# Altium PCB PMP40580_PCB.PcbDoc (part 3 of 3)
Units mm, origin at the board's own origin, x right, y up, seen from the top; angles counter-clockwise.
Board outline 215 x 165 mm, 2 copper layers (Top Layer, Bottom Layer), stack 1.575 mm thick; 235 components, 90 nets, 527 pads, 0 vias.
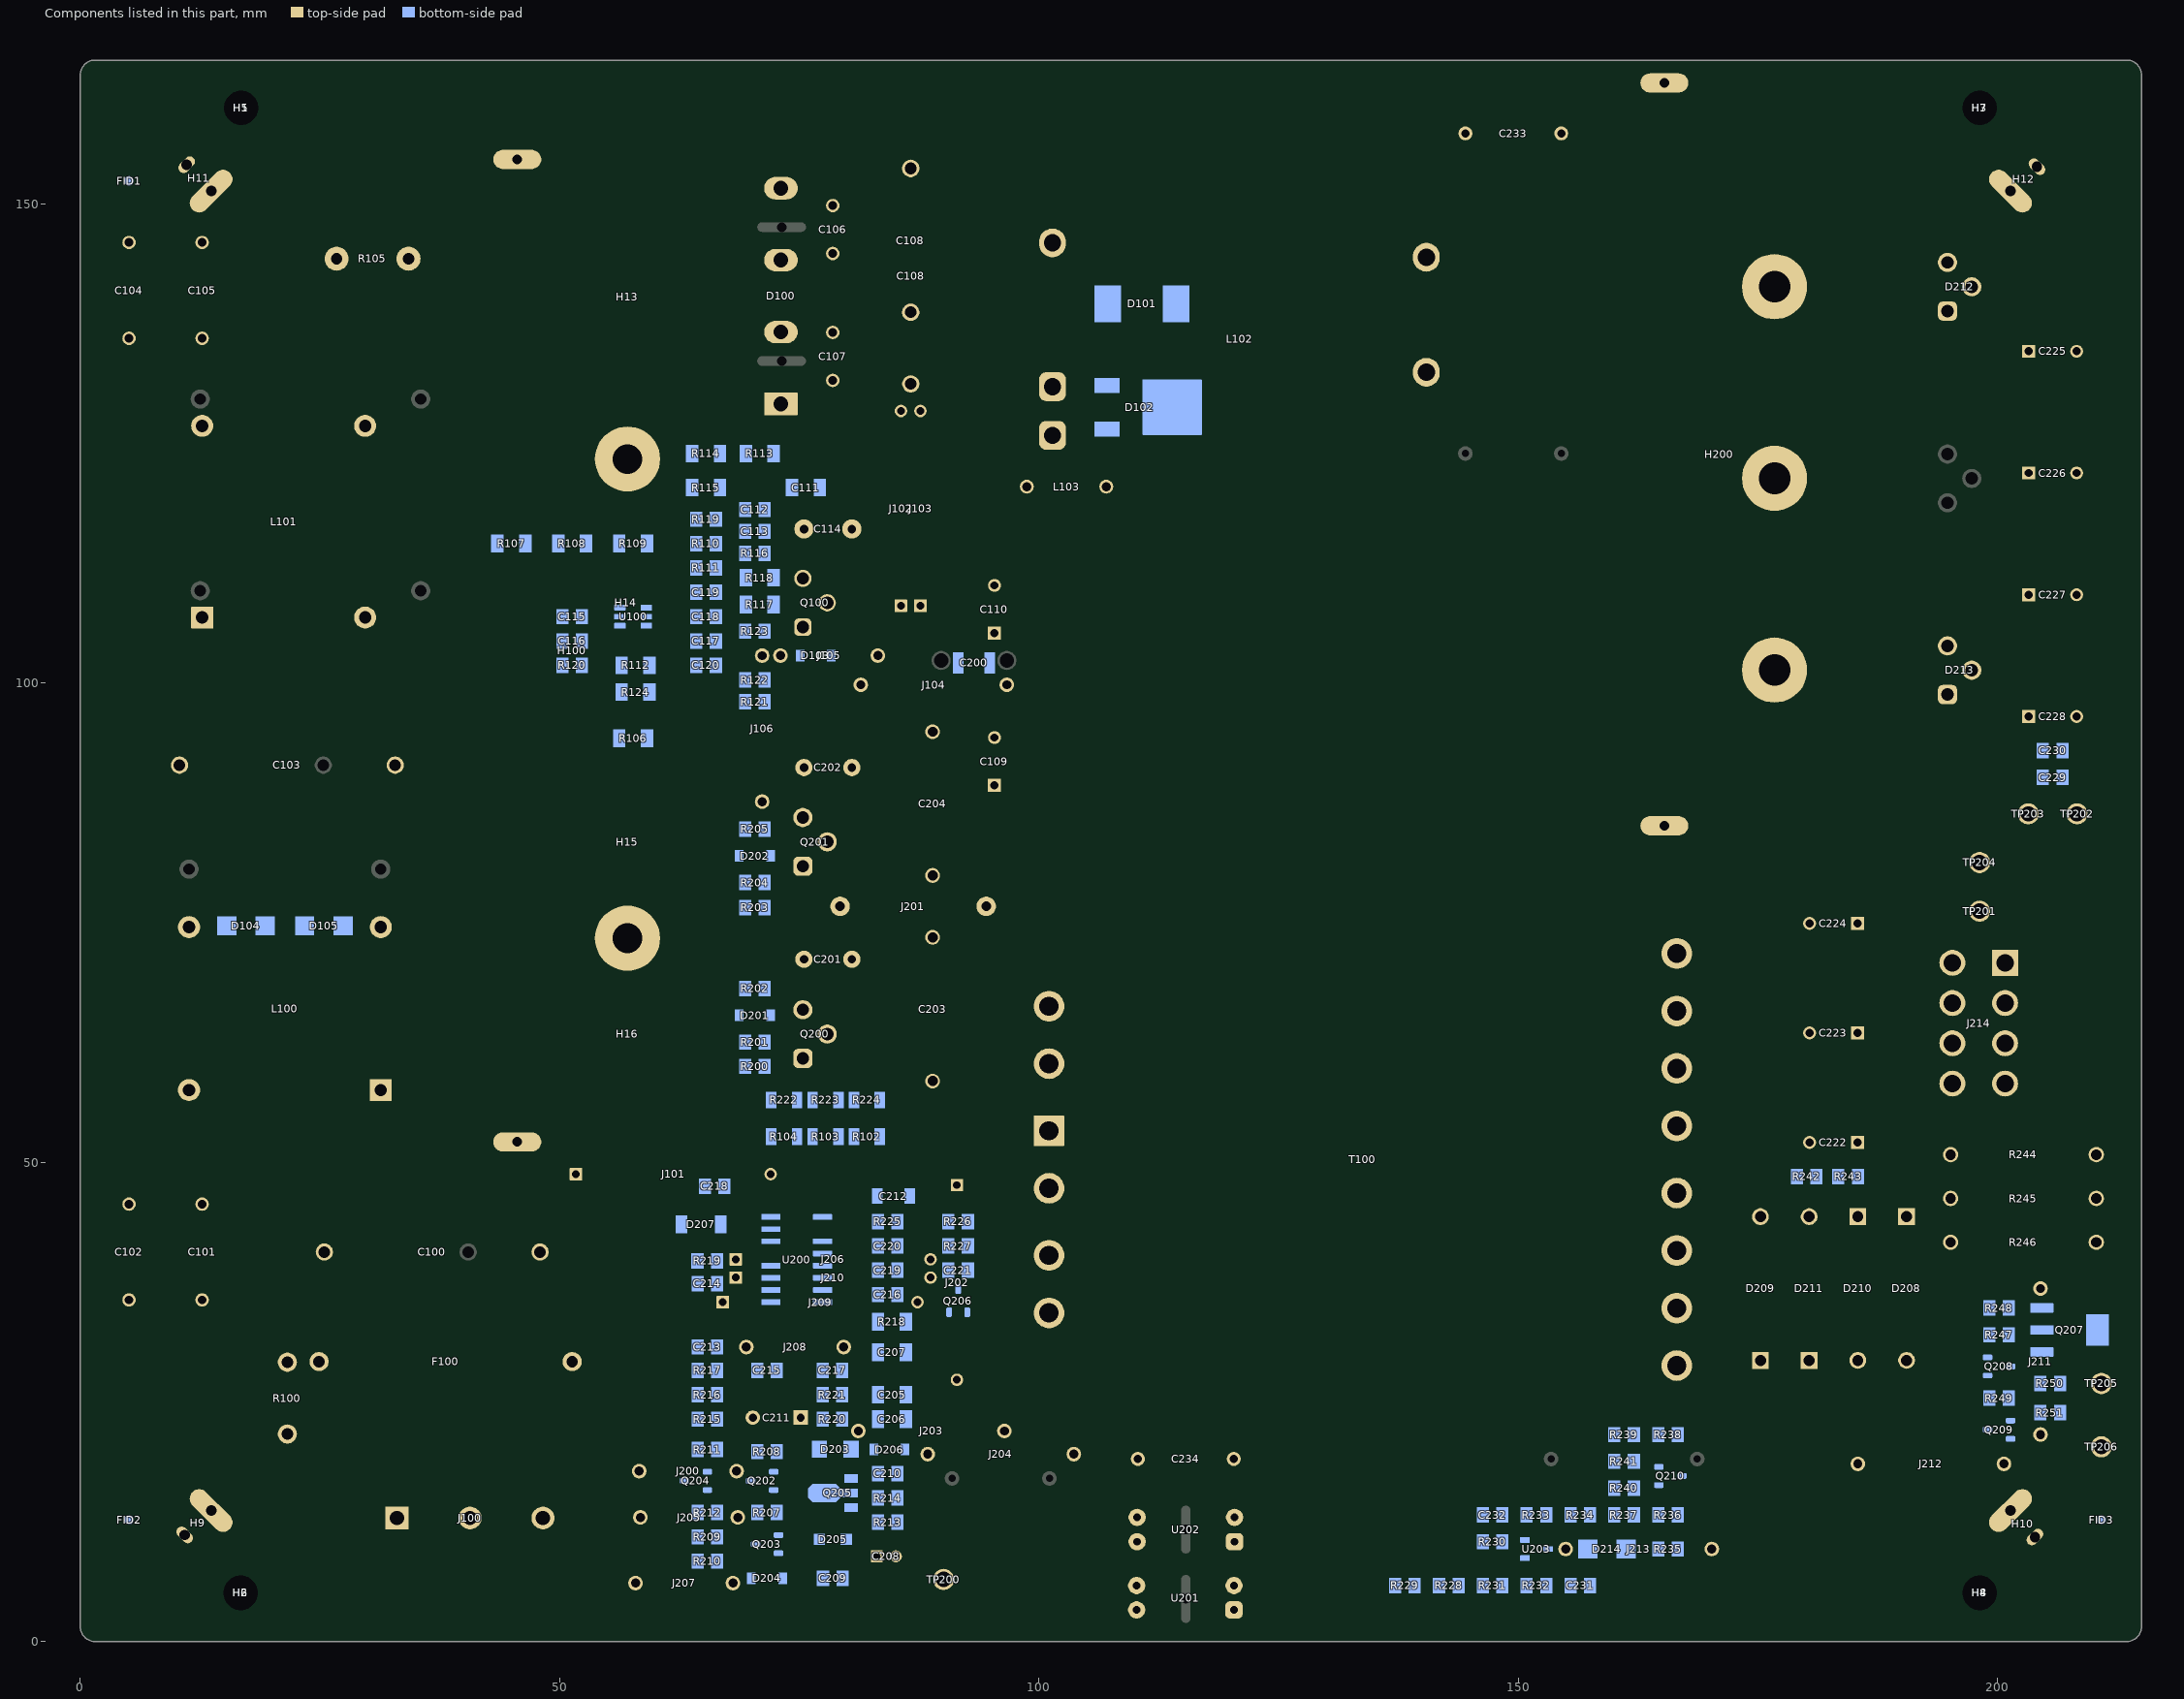
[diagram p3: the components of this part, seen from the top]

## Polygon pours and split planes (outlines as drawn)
PGND on Bottom Layer "Bottom Layer-No Net 15" (solid, pour order 78): 97.028,20.574 98.552,22.098 98.552,35.306 100.076,36.83 110.998,36.83 110.998,16.002 110.236,15.24 97.79,15.24 97.028,16.002
PGND on Bottom Layer "Bottom Layer-PGND" (solid, remove dead copper, pour order 70): 67.421,115.316 76.2,106.661 76.2,52.705 81.661,47.244 91.948,47.244 91.948,4.445 55.88,4.445 55.88,55.88 52.07,59.69 52.07,106.045 63.119,106.045 63.754,106.68 63.754,115.316
NetC112_2 on Bottom Layer "Source" (solid, remove dead copper, pour order 18): 73.406,106.934 76.725,110.253 76.725,111.196 76.454,111.467 76.454,114.554 72.136,118.872 70.824,118.872 70.87,107.438 71.374,106.934
PGND on Bottom Layer "Bottom Layer-PGND2" (solid, remove dead copper, pour order 68): 139.065,85.09 148.59,85.09 150.749,87.249 150.749,99.568 150.749,114.3 145.415,119.634 145.415,165 72.036,165 69.596,162.56 69.596,149.606 70.358,148.844 79.375,148.844 82.55,152.019 82.55,157.48 86.36,161.29 135.89,161.29 139.065,158.115
VCC on Bottom Layer "Bottom Layer-VCC" (solid, remove dead copper, pour order 66): 78.105,9.144 78.105,11.099 76.107,13.096 76.107,20.828 78.867,20.828 78.867,14.608 78.867,9.512 78.981,9.398 82.169,9.398 84.836,12.065 84.836,15.24 85.09,15.494 85.471,15.494 85.725,15.24 85.725,10.668 83.058,8.001 79.248,8.001
NetC117_1 on Bottom Layer "Bottom Layer-PFCVCC" (solid, remove dead copper, pour order 62): 58.801,106.426 58.547,106.172 58.547,102.108 59.817,100.838 64.643,100.838 64.643,104.394 62.611,106.426
SGND on Bottom Layer "Bottom Layer-No Net 12" (solid, remove dead copper, pour order 56): 14.478,16.51 13.462,17.526 13.462,32.004 17.018,35.56 17.018,36.83 16.51,37.338 0,37.338 0,0 22.098,0 22.098,8.89
SGND on Bottom Layer "Bottom Layer-No Net 12" (solid, remove dead copper, pour order 54): 0,144.399 15.444,144.399 16.637,145.592 16.637,151.892 22.86,158.115 22.86,165 0,165
NetC106_2 on Bottom Layer "Bottom Layer-No Net 10" (solid, remove dead copper, pour order 52): 79.756,145.034 78.994,145.796 69.342,145.796 67.818,147.32 33.274,147.32 32.512,146.558 32.512,143.256 33.274,142.494 79.212,142.494 79.756,143.038
NetC107_1 on Bottom Layer "Bottom Layer-No Net 11" (solid, remove dead copper, pour order 50): 79.756,135.89 79.269,135.403 69.109,135.403 67.056,133.35 55.626,133.35 39.476,117.2 39.476,110.342 33.274,104.14 28.575,104.14 26.67,106.045 26.67,111.76 37.084,122.174 53.086,138.176 79.248,138.176 79.756,137.668
NetD102_1 on Bottom Layer "Bottom Layer-No Net" (solid, pour order 24): 106.426,119.38 105.801,120.005 105.801,132.471 106.172,132.842 108.204,132.842 108.712,132.334 108.712,119.38
PGND on Bottom Layer "Bottom Layer-No Net" (solid, remove dead copper, pour order 8): 83.566,108.288 87.038,111.76 93.218,111.76 96.11,111.76 96.52,111.35 96.52,109.347 95.885,108.712 93.98,108.712 92.202,106.934 92.202,99.314 96.52,94.996 96.52,93.345 95.631,92.456 84.836,92.456 83.185,94.107 79.514,94.107 77.47,92.063 77.47,90.932 77.47,85.836 76.216,84.582 74.906,84.582 72.898,86.59 72.898,91.44 78.486,97.028 80.264,98.806 80.264,101.346 80.264,104.986
HS on Bottom Layer "HS" (solid, pour order 6): 79.502,84.582 79.502,80.264 73.406,74.168 69.469,74.168 68.707,73.406 68.707,70.739 74.676,64.77 76.458,64.77 78.359,66.671 78.359,73.533 81.28,76.454 81.28,86.614 81.28,92.075 79.883,92.075 79.502,91.694
HS on Bottom Layer "Bottom Layer-No Net" (solid, pour order 4): 98.425,64.806 98.425,59.055 99.441,58.039 102.997,58.039 104.14,59.182 104.14,64.77 104.14,76.18 101.602,78.74 93.726,78.74 92.837,77.851 92.837,74.803 98.425,69.215
NetC203_2 on Bottom Layer "Bottom Layer-No Net" (solid, pour order 2): 102.87,55.88 103.378,55.88 104.14,55.118 104.14,51.562 103.378,50.8 102.87,50.8 95.377,50.8 93.472,48.895 92.583,48.895 92.4,49.078 92.4,63.556 87.884,68.072 87.884,80.772 88.392,81.28 90.297,81.28 90.805,80.772 90.805,73.707 96.436,68.076 96.436,59.52 96.436,58.25 98.806,55.88
PFC_DC+ on Bottom Layer "PFC_DC" (solid, pour order 0): 135.255,86.995 133.604,85.344 102.108,85.344 100.076,83.312 87.122,83.312 85.852,82.042 85.852,66.818 90.17,62.5 90.17,57.15 89.789,56.769 88.011,56.769 85.344,59.436 80.628,59.436 77.47,62.594 77.47,64.262 79.502,66.294 79.502,71.755 83.312,75.565 83.312,85.852 87.884,90.424 97.155,90.424 98.679,91.948 98.679,95.631 94.234,100.076 94.234,106.68 97.028,106.68 110.744,120.396 110.744,138.43 110.883,138.569 110.883,156.603 112.395,158.115 133.35,158.115 135.255,156.21 135.255,105.791
NetC107_2 on Bottom Layer "Bottom Layer-No Net" (solid, pour order 10): 70.612,130.556 71.499,131.443 75.82,131.446 77.216,132.842 80.264,132.842 81.269,131.837 81.269,131.805 82.296,130.778 82.296,126.746 84.074,124.968 89.154,124.968 91.186,127 91.186,147.066 85.09,153.162 85.09,156.464 86.741,158.115 96.361,158.115 108.712,145.764 108.712,139.16 108.712,137.414 108.712,136.906 108.204,136.398 99.822,136.398 97.79,138.43 97.79,147.828 91.44,154.178 88.265,154.178 88.265,153.67 91.186,153.67 97.282,147.574 97.282,125.476 92.583,120.777 81.915,120.777 75.692,127 71.12,127 70.612,127.508
PGND on Bottom Layer "Bottom Layer-No Net" (solid, pour order 12): 70.358,148.844 69.596,149.606 69.596,154.178 70.358,154.94 80.01,154.94 88.9,146.05 88.9,127.635 88.265,127 84.94,127 84.328,127.612 84.328,143.764 79.248,148.844
NetC111_1 on Bottom Layer "Bottom Layer-No Net" (solid, pour order 14): 78.999,117.597 76.708,119.888 76.708,120.83 78.793,118.745 78.863,118.745 93.345,118.745 99.314,124.714 99.314,132.842 99.822,133.35 103.124,133.35 103.759,132.715 103.759,122.301 95.885,114.427 86.741,114.427 78.994,106.68 78.384,106.68 77.216,107.848 77.216,108.912 78.999,110.695
NetD208_2 on Bottom Layer "Bottom Layer-No Net 2" (solid, remove dead copper, pour order 32): 171.577,40.767 176.784,35.56 188.357,35.56 191.897,32.131 191.897,28.575 191.262,27.94 189.23,27.94 188.595,28.575 188.595,30.861 187.325,32.131 180.213,32.131 178.816,32.131 177.165,30.48 177.165,28.575 176.53,27.94 173.99,27.94 173.355,28.575 173.355,33.655 168.91,38.1 168.656,38.354 165.1,38.354 164.084,39.37 164.084,42.418 164.846,43.18 169.164,43.18 169.99,42.355
NetD210_2 on Bottom Layer "Bottom Layer-No Net 2" (solid, remove dead copper, pour order 34): 172.72,32.385 172.72,28.575 173.99,27.305 177.165,27.305 177.8,27.94 177.8,29.845 179.07,31.115 186.055,31.115 187.325,29.845 187.325,26.67 186.055,25.4 171.45,25.4 169.164,27.686 169.164,30.226 167.64,31.75 165.1,31.75 164.084,32.766 164.084,36.449 164.973,37.338 167.767,37.338
12V on Bottom Layer "Bottom Layer-No Net 3" (solid, remove dead copper, pour order 36): 197.612,145.288 198.374,146.05 203.2,146.05 205.232,144.018 205.232,84.582 204.47,83.82 198.374,83.82 197.612,84.582
150V on Bottom Layer "Bottom Layer-No Net 4" (solid, remove dead copper, pour order 38): 183.388,42.418 183.388,39.243 184.15,38.481 191.516,38.481 192.278,39.243 192.278,42.672 192.278,45.212 186.69,50.8 186.69,73.66 187.706,74.676 192.532,74.676 193.04,74.168 193.04,72.136 191.262,70.358 188.214,70.358 187.452,69.596 187.452,51.308 193.04,45.72 193.04,27.686 193.294,27.432 194.056,27.432 194.056,39.116 196.342,41.402 196.342,51.054 195.589,51.807 190.255,51.807 188.468,53.594 188.468,68.834 188.976,69.342 202.184,69.342 202.946,70.104 202.946,75.184 200.152,77.978 186.436,77.978 183.388,74.93
SGND on Bottom Layer "Bottom Layer-No Net 5" (solid, remove dead copper, pour order 40): 120.904,76.962 119.38,75.438 119.38,73.533 119.38,35.941 119.38,0 215,0 215,164.984 214.884,165.1 158.115,165.1 158.115,165 153.543,165 153.543,122.936 158.877,117.602 158.877,79.248 156.591,76.962
NetC103_2 on Bottom Layer "Bottom Layer-No Net 7" (solid, remove dead copper, pour order 42): 28.448,73.152 32.766,73.152 34.29,74.676 34.29,92.71 19.685,107.315 19.685,130.937 13.462,137.16 11.938,137.16 11.43,136.652 11.43,135.636 17.145,129.921 17.145,122.809 10.668,116.332 10.668,103.632 27.178,87.122 27.178,74.422
NetC103_1 on Bottom Layer "Bottom Layer-No Net 8" (solid, remove dead copper, pour order 44): 14.732,74.168 14.732,75.692 12.954,77.47 12.954,97.3 8.128,102.126 8.128,120.142 14.605,126.619 14.605,128.905 6.35,137.16 4.318,137.16 3.81,136.652 3.81,75.184 5.842,73.152 13.716,73.152
Neutral on Bottom Layer "Bottom Layer-No Net 9" (solid, remove dead copper, pour order 46): 38.862,10.16 42.164,10.16 43.18,11.176 43.18,27.94 49.53,34.29 49.53,41.656 25.146,66.04 8.128,66.04 3.81,61.722 3.81,44.704 4.318,44.196 6.687,44.196 7.366,44.875 7.366,59.944 9.652,62.23 23.495,62.23 38.608,47.117 38.608,26.416 35.814,23.622 20.828,23.622 20.066,22.86 20.066,20.32 20.828,19.558 36.068,19.558 37.846,17.78 37.846,11.176
NetD103_2 on Bottom Layer "Gate" (solid, remove dead copper, pour order 20): 74.294,106.906 74.449,107.061 76.387,107.061 76.514,106.934 78.74,104.708 78.74,102.362 73.66,97.282 70.612,97.282 70.612,98.895 72.927,98.895 76.962,102.93 76.962,103.378 75.718,104.622 70.751,104.622 70.751,106.057 70.866,106.172 73.56,106.172
NetC100_1 on Bottom Layer "Bottom Layer-No Net 6" (solid, remove dead copper, pour order 72): 20.828,27.178 26.67,27.178 27.94,28.448 27.94,51.435 19.685,59.69 10.922,59.69 9.906,58.674 9.906,44.958 10.668,44.196 13.716,44.196 14.478,44.958 14.478,49.022 12.192,51.308 12.192,55.626 12.954,56.388 17.272,56.388 23.622,50.038 23.622,33.02 20.066,29.464 20.066,27.94
Line on Bottom Layer "Bottom Layer-No Net 13" (solid, pour order 74): 51.816,10.16 52.832,11.176 52.832,29.972 52.07,30.734 50.038,30.734 45.72,26.416 45.72,11.176 46.736,10.16
NetL101_3 on Bottom Layer "Bottom Layer-No Net 14" (solid, pour order 76): 37.465,134.62 29.21,142.875 29.21,146.685 28.575,147.32 24.765,147.32 24.13,146.685 24.13,126.492 26.162,124.46 32.385,124.46 37.465,129.54

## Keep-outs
Keep-Out Layer:
  lines w0.127: 0,1.532 ccw(c1.532,1.532) 1.532,0 213.468,0 ccw(c213.468,1.532) 215,1.532 215,163.468 ccw(c213.468,163.468) 213.468,165 1.532,165 ccw(c1.532,163.468) 0,163.468 0,1.532 ; 2.758,5.174 ccw(c5.158,5.174) 5.158,2.774 ccw(c5.158,5.174) 7.558,5.174 ccw(c5.158,5.174) 5.158,7.574 ccw(c5.158,5.174) 2.758,5.174 ; 2.758,159.81 ccw(c5.158,159.81) 5.158,157.41 ccw(c5.158,159.81) 7.558,159.81 ccw(c5.158,159.81) 5.158,162.21 ccw(c5.158,159.81) 2.758,159.81 ; 74.964,62.976 cw(c75.368,63.38) 74.964,63.784 77.504,66.324 cw(c77.908,65.92) 78.312,65.516 76.176,63.38 78.312,61.244 cw(c77.908,60.84) 77.504,60.436 74.964,62.976 ; 74.964,83.03 cw(c75.368,83.434) 74.964,83.838 77.504,86.378 cw(c77.908,85.974) 78.312,85.57 76.176,83.434 78.312,81.298 cw(c77.908,80.894) 77.504,80.49 74.964,83.03 ; 74.964,107.976 cw(c75.368,108.38) 74.964,108.784 77.504,111.324 cw(c77.908,110.92) 78.312,110.516 76.176,108.38 78.312,106.244 cw(c77.908,105.84) 77.504,105.436 74.964,107.976 ; 194.236,140.947 cw(c194.64,141.351) 194.236,141.755 196.776,144.295 cw(c197.18,143.891) 197.584,143.487 195.448,141.351 197.584,139.215 cw(c197.18,138.811) 196.776,138.407 194.236,140.947 ; 194.241,120.881 cw(c194.645,121.285) 194.241,121.689 196.781,124.229 cw(c197.185,123.825) 197.589,123.421 195.453,121.285 197.589,119.149 cw(c197.185,118.745) 196.781,118.341 194.241,120.881 ; 194.363,100.942 cw(c194.767,101.346) 194.363,101.75 196.903,104.29 cw(c197.307,103.886) 197.711,103.482 195.575,101.346 197.711,99.21 cw(c197.307,98.806) 196.903,98.402 194.363,100.942 ; 207.418,5.174 ccw(c209.818,5.174) 209.818,2.774 ccw(c209.818,5.174) 212.218,5.174 ccw(c209.818,5.174) 209.818,7.574 ccw(c209.818,5.174) 207.418,5.174 ; 207.418,159.81 ccw(c209.818,159.81) 209.818,157.41 ccw(c209.818,159.81) 212.218,159.81 ccw(c209.818,159.81) 209.818,162.21 ccw(c209.818,159.81) 207.418,159.81
  lines w0.254: 0,1.532 ccw(c1.532,1.532) 1.532,0 213.468,0 ccw(c213.468,1.532) 215,1.532 215,163.468 ccw(c213.468,163.468) 213.468,165 1.532,165 ccw(c1.532,163.468) 0,163.468 0,1.532 ; 2.758,5.174 ccw(c5.158,5.174) 5.158,2.774 ccw(c5.158,5.174) 7.558,5.174 ccw(c5.158,5.174) 5.158,7.574 ccw(c5.158,5.174) 2.758,5.174 ; 2.758,159.81 ccw(c5.158,159.81) 5.158,157.41 ccw(c5.158,159.81) 7.558,159.81 ccw(c5.158,159.81) 5.158,162.21 ccw(c5.158,159.81) 2.758,159.81 ; 207.418,5.174 ccw(c209.818,5.174) 209.818,2.774 ccw(c209.818,5.174) 212.218,5.174 ccw(c209.818,5.174) 209.818,7.574 ccw(c209.818,5.174) 207.418,5.174 ; 207.418,159.81 ccw(c209.818,159.81) 209.818,157.41 ccw(c209.818,159.81) 212.218,159.81 ccw(c209.818,159.81) 209.818,162.21 ccw(c209.818,159.81) 207.418,159.81
  text ".Layer_Name" at 14.656,-51.321 h1.52

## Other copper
Top Layer:
  text ".Layer_Name" at 14.656,-51.321 h1.52
Bottom Layer:
  rectangle net SGND: 163.576,46.355 169.418,47.117
  rectangle net NetQ207_2: 203.2,31.496 211.328,33.528
  region net SGND: 166.878,46.228 166.878,49.7 166.116,49.7 166.116,46.228
  region net PGND: 140.746,142.342 140.746,146.957 139.984,146.957 139.984,142.342
  rectangle net PGND: 140.462,144.12 142.821,144.882
  region net PGND: 140.746,130.342 140.746,134.957 139.984,134.957 139.984,130.342
  rectangle net PGND: 140.208,132.12 142.821,132.882
  pour cut-out: 197.612,109.474 203.2,109.474 203.2,108.966 197.612,108.966
  region net NetD203_2: 78.867,24.003 80.645,24.003 81.915,22.733 81.915,21.209 80.264,19.558 79.502,19.558 79.502,21.717 78.867,22.352
  pour cut-out: 103.505,63.246 104.14,62.611 104.14,64.135 103.505,63.5 99.187,63.5 98.425,64.262 98.425,62.484 99.187,63.246
  region: 112.018,53.611
  region: 112.018,53.611
  region: 112.018,53.611
  region: 112.018,53.611
  region: 112.018,53.611
  region: 112.018,53.611
  pour cut-out: 103.251,128.27 103.378,128.27 103.759,127.889 103.759,128.768 103.388,128.397 99.695,128.397 99.314,128.778 99.314,127.889 99.695,128.27 99.822,128.27
  region net VCC: 82.195,8.011 82.427,8.011 84.08,9.664 83.651,10.093 82.864,10.093 82.195,9.424
  region net NetC211_1: 75.946,28.829 75.438,28.829 74.422,27.813 74.422,24.09 75.144,23.368 75.946,24.17
  region net RVCC: 71.882,22.479 69.977,20.574 69.977,17.217 68.834,16.074 68.834,15.621 69.977,14.478 69.977,12.7 71.247,12.7 71.247,20.574 73.66,22.987 73.66,27.813 74.93,29.083 74.93,31.534 74.46,31.534 71.882,28.956
  region net PS_ON: 142.621,4.064 142.621,4.572 142.748,4.699 142.875,4.699 145.034,2.54 145.034,2.286 144.399,2.286
  pour cut-out: 94.996,83.312 94.996,87.63 95.504,87.63 95.504,83.312
  region net DRV: 68.326,97.536 68.834,98.044 68.834,101.092 69.596,101.092 69.977,100.711 69.977,97.282 69.723,97.028 58.674,97.028 58.166,97.536 58.166,97.79 58.166,103.124 57.404,103.886 57.404,105.484 57.404,106.426 57.201,106.629 55.601,106.629 55.499,106.731 55.499,107.137 55.601,107.239 55.617,107.239 57.506,107.239 57.892,106.852 57.892,104.033 58.42,103.505 58.42,97.841 58.725,97.536
  pour cut-out: 209.296,134.874 214.815,134.874 214.815,134.366 209.296,134.366
  pour cut-out: 209.296,122.174 214.884,122.174 214.884,121.666 209.296,121.666
  pour cut-out: 209.296,109.474 214.884,109.474 214.884,108.966 209.296,108.966
  pour cut-out: 209.296,96.774 214.884,96.774 214.884,96.266 209.296,96.266
  pour cut-out: 197.612,96.647 202.438,96.647 202.438,96.266 197.612,96.266
  region net HS: 76.2,76.962 81.28,76.962 81.28,88.578 79.502,88.578 79.502,86.8 76.552,83.85 76.552,83.058 78.994,80.616 78.994,79.756
  region net HS: 71.12,73.66 72.898,73.66 74.168,74.93 74.93,74.93 77.47,74.93 77.47,66.294 75.946,64.77 74.676,64.77 73.025,66.421 73.025,69.088 72.263,69.85 69.215,69.85 68.707,70.358 68.707,71.247
  region net PGND: 74.422,84.582 75.708,84.582 77.47,86.344 77.47,87.884 74.523,87.884 73.533,86.894 73.533,85.471
  region net NetC112_2: 76.962,116.078 76.2,116.84 73.982,116.84 72.598,115.456 72.598,110.482 74.376,108.704 74.376,108.402 74.625,108.153 76.962,110.49
  region net NetD202_2: 71.374,75.692 71.882,75.692 76.708,80.518 76.708,81.28 72.505,85.483 70.739,85.483 70.739,82.356 73.024,80.071 73.029,78.49 71.374,76.835
  region net NetD201_2: 76.962,59.962 76.962,60.978 71.984,65.956 71.984,68.58 70.712,68.58 70.712,65.686 72.648,63.751 72.648,62.386 72.65,61.474 71.628,60.452 71.628,59.436 76.436,59.436
  region net NetC111_1: 79.004,113.522 79.004,110.7 76.962,108.658 76.962,108.102 78.13,106.934 79.248,106.934 82.296,109.982 82.296,113.538 79.02,113.538
  region net PFC_DC+: 80.757,59.444 80.112,59.444 76.454,63.102 76.454,63.658 79.502,66.706 79.502,68.524 80.066,68.524 82.042,66.548 82.042,60.729 85.067,60.729 87.757,58.039 87.757,57.023 85.336,59.444
  pour cut-out: 26.67,91.694 31.242,91.694 31.242,91.186 26.67,91.186
  pour cut-out: 41.91,40.894 46.482,40.894 46.482,40.386 41.91,40.386
  pour cut-out: 135.255,99.568 99.06,99.568 99.06,100.076 135.255,100.076
  region net NetD103_2: 76.717,103.641 76.717,102.607 76.731,102.593 77.216,102.108 78.486,102.108 78.74,102.362 78.74,104.648 76.327,107.061 74.549,107.061 73.66,106.172 71.374,106.172 71.374,104.648 75.711,104.648
  region net 150V: 183.896,50.8 185.166,49.53 185.166,47.498 183.642,45.974 186.436,45.974 186.436,50.292 185.928,50.8
  pour cut-out: 3.81,91.694 8.636,91.694 8.636,91.186 3.81,91.186
  text ".Layer_Name" at 14.656,-51.321 h1.52

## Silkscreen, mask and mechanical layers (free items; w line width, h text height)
Top Overlay:
  region: 61.849,161.62 54.229,161.62 54.229,159.08 61.849,159.08
  lines w0.127: 0,37.338 16.51,37.338 17.018,36.83 17.018,35.56 13.462,32.004 13.462,17.526 22.098,8.89 22.098,0 ; 0,43.942 19.127,43.942 23.622,39.447 23.622,33.02 20.066,29.464 20.066,20.066 28.702,11.43 28.702,0 ; 0,137.718 17.907,137.718 22.987,142.798 22.987,149.098 29.591,155.702 29.591,165 ; 0,144.399 15.444,144.399 16.637,145.592 16.637,151.688 22.987,158.038 22.987,165 ; 111.316,0 111.316,82.741 113.665,85.09 150.749,85.09 150.749,114.3 145.415,119.634 145.415,165 ; 119.38,0 119.38,75.565 120.904,77.089 156.591,77.089 158.75,79.248 158.75,117.729 153.543,122.936 153.543,165 ; 22.098,0 22.098,0 ; 145.415,165 145.415,165
  lines w0.15: 10.34,91.44 17.09,91.44 ; 17.14,90.64 17.14,92.24 ; 18.54,90.64 18.54,92.24 ; 18.59,91.44 25.34,91.44 ; 21.59,22.733 21.59,23.9 21.09,24.15 22.09,24.65 21.09,25.15 22.09,25.65 21.09,26.15 22.09,26.65 21.59,26.9 21.59,28.067 ; 25.453,40.64 32.203,40.64 ; 26.85,29.21 35.1,29.21 cw(c36.6,29.21) 38.1,29.21 ccw(c39.6,29.21) 41.1,29.21 49.35,29.21 ; 27.813,144.272 28.98,144.272 29.23,144.772 29.73,143.772 30.23,144.772 30.73,143.772 31.23,144.772 31.73,143.772 31.98,144.272 33.147,144.272 ; 32.253,39.84 32.253,41.44 ; 33.653,39.84 33.653,41.44 ; 33.703,40.64 40.453,40.64 ; 70.993,23.368 72.263,23.368 ; 72.263,22.606 72.263,24.13 ; 73.025,22.606 73.025,24.13 ; 73.025,23.368 74.295,23.368 ; 85.826,145.512 87.426,145.512 ; 85.826,146.912 87.426,146.912 ; 86.626,138.712 86.626,145.462 ; 86.626,146.962 86.626,153.712 ; 88.1,65.277 89.7,65.277 ; 88.1,66.677 89.7,66.677 ; 88.1,86.724 89.7,86.724 ; 88.1,88.124 89.7,88.124 ; 88.9,58.477 88.9,65.227 ; 88.9,66.727 88.9,73.477 ; 88.9,79.924 88.9,86.674 ; 88.9,88.174 88.9,94.924 ; 147.574,157.353 148.844,157.353 ; 148.844,156.591 148.844,158.115 ; 149.606,156.591 149.606,158.115 ; 149.606,157.353 150.876,157.353 ; 198.12,41.656 201.192,41.656 201.442,42.156 201.942,41.156 202.442,42.156 202.942,41.156 203.442,42.156 203.942,41.156 204.192,41.656 207.264,41.656 ; 198.12,46.228 201.192,46.228 201.442,46.728 201.942,45.728 202.442,46.728 202.942,45.728 203.442,46.728 203.942,45.728 204.192,46.228 207.264,46.228 ; 198.12,50.8 201.192,50.8 201.442,51.3 201.942,50.3 202.442,51.3 202.942,50.3 203.442,51.3 203.942,50.3 204.192,50.8 207.264,50.8
  text "'.PRJ_Number'.PCB_Rev-" at 39.37,159.481 h2.75
  text "12V/5A" at 202.184,82.169 h2.54
  text "150V/0.8A" at 200.914,75.438 h2.54
  text "150V" at 188.214,69.977 h2.54
  text "GND" at 188.468,65.786 h2.54
  text "12V" at 189.497,61.468 h2.54
  text "GND" at 188.468,57.404 h2.54
  text "PSON" at 207.772,29.464 h2.54
  text "90~264Vac, 2.5A / 50Hz/60Hz" at 30.48,16.764 h3.05
  text "PGND" at 88.011,2.54 h2.54
  text "E" at 32.385,0.635 h2.54
  text "N" at 40.005,0.635 h2.54
  text "L" at 47.625,0.635 h2.54
  text ".Layer_Name" at 14.656,-51.321 h1.52
Bottom Overlay:
  drawing of 166 lines, arcs and shapes, not listed
  text "+" at 202.692,135.636 h2.54
  text "+" at 75.311,128.27 h2.54
  text "+" at 202.692,122.936 h2.54
  text "+" at 202.692,110.236 h2.54
  text "+" at 97.282,104.394 h2.54
  text "+" at 202.692,97.536 h2.54
  text "+" at 97.282,88.646 h2.54
  text "12V" at 200.787,85.598 h2.54
  text "GND" at 210.585,80.391 h2.54
  text "+" at 88.392,76.962 h2.54
  text "+" at 184.785,76.2 h2.54
  text "150V" at 205.74,75.438 h2.54
  text "150V" at 208.274,69.977 h2.54
  text "GND" at 208.039,65.786 h2.54
  text "+" at 184.785,64.77 h2.54
  text "12V" at 207.01,61.595 h2.54
  text "GND" at 208.039,57.404 h2.54
  text "+" at 88.392,55.372 h2.54
  text "+" at 184.785,53.34 h2.54
  text "+" at 74.676,24.638 h2.54
  text "N" at 40.005,9.246 h2.54 r180
  text "E" at 33.655,7.62 h2.54
  text "L" at 48.895,7.62 h2.54
  text "+" at 82.55,6.35 h2.54
  text ".Layer_Name" at 14.656,-51.321 h1.52
Top Paste:
  text ".Layer_Name" at 14.656,-51.321 h1.52
Bottom Paste:
  text ".Layer_Name" at 14.656,-51.321 h1.52
Top Solder:
  text ".Layer_Name" at 14.656,-51.321 h1.52
  text ".Layer_Name" at 14.656,-51.321 h1.52
Bottom Solder:
  rectangle: 98.425,62.611 104.14,64.135
  rectangle: 99.324,127.772 103.749,128.905
  rectangle: 133.51,116.41 134.81,119.81
  rectangle: 139.41,116.41 140.71,119.81
  rectangle: 133.51,111.33 134.81,114.73
  rectangle: 139.41,111.33 140.71,114.73
  rectangle: 133.51,106.25 134.81,109.65
  rectangle: 139.41,106.25 140.71,109.65
  rectangle: 133.51,101.17 134.81,104.57
  rectangle: 139.41,101.17 140.71,104.57
  rectangle: 133.51,93.55 134.81,96.95
  rectangle: 139.41,93.55 140.71,96.95
  rectangle: 133.51,88.47 134.81,91.87
  rectangle: 139.41,88.47 140.71,91.87
  rectangle: 139.41,121.49 140.71,124.89
  rectangle: 133.51,121.49 134.81,124.89
  rectangle: 133.51,126.57 134.81,129.97
  rectangle: 139.41,126.57 140.71,129.97
  rectangle: 207.239,101.17 209.29,104.57
  rectangle: 202.09,101.17 204.241,104.57
  rectangle: 202.09,113.87 204.241,117.27
  rectangle: 207.239,113.87 209.29,117.27
  rectangle: 202.09,126.57 204.241,129.97
  rectangle: 207.239,126.57 209.29,129.97
  rectangle: 179.23,68.15 181.381,71.55
  rectangle: 184.379,68.15 186.43,71.55
  rectangle: 179.23,56.72 181.381,60.12
  rectangle: 184.379,56.72 186.43,60.12
  region: 0.127,144.322 0.127,137.718 17.907,137.718 22.987,142.798 22.987,149.098 29.591,155.702 29.591,165.05 22.987,165.05 22.987,158.038 16.637,151.688 16.637,145.592 15.367,144.322
  region: 0,43.942 19.127,43.942 23.622,39.447 23.622,33.02 20.066,29.464 20.066,20.066 28.702,11.43 28.702,0 22.098,0 22.098,8.89 13.462,17.526 13.462,32.004 17.018,35.56 17.018,36.83 16.51,37.338 0,37.338
  region: 148.717,85.09 150.749,87.122 150.749,114.3 145.415,119.634 145.415,165 153.543,165 153.543,122.936 158.75,117.729 158.75,80.391 158.75,79.248 156.591,77.089 120.904,77.089 119.38,75.565 119.38,35.941 119.38,0 111.316,0 111.316,39.18 111.316,82.741 113.665,85.09
  text ".Layer_Name" at 14.656,-51.321 h1.52
Drill Guide:
  text ".Layer_Name" at 14.656,-51.321 h1.52
M1 Board Outline:
  lines w0.254: 0,1.532 ccw(c1.532,1.532) 1.532,0 ; 0,1.532 ccw(c1.532,1.532) 1.532,0 ; 0,1.532 ccw(c1.532,1.532) 1.532,0 ; 0,1.532 0,163.468 ; 0,1.532 0,163.468 ; 0,1.532 0,163.468 ; 0,163.468 cw(c1.532,163.468) 1.532,165 ; 0,163.468 cw(c1.532,163.468) 1.532,165 ; 0,163.468 cw(c1.532,163.468) 1.532,165 ; 1.532,0 213.468,0 ; 1.532,0 213.468,0 ; 1.532,0 213.468,0 ; 1.532,165 213.468,165 ; 1.532,165 213.468,165 ; 1.532,165 213.468,165 ; 2.758,5.174 ccw(c5.158,5.174) 5.158,2.774 ; 2.758,5.174 cw(c5.158,5.174) 5.158,7.574 ; 2.758,5.174 ccw(c5.158,5.174) 5.158,2.774 ; 2.758,5.174 cw(c5.158,5.174) 5.158,7.574 ; 2.758,159.81 ccw(c5.158,159.81) 5.158,157.41 ; 2.758,159.81 cw(c5.158,159.81) 5.158,162.21 ; 2.758,159.81 ccw(c5.158,159.81) 5.158,157.41 ; 2.758,159.81 cw(c5.158,159.81) 5.158,162.21 ; 5.158,2.774 ccw(c5.158,5.174) 7.558,5.174 ; 5.158,2.774 ccw(c5.158,5.174) 7.558,5.174 ; 5.158,7.574 cw(c5.158,5.174) 7.558,5.174 ; 5.158,7.574 cw(c5.158,5.174) 7.558,5.174 ; 5.158,157.41 ccw(c5.158,159.81) 7.558,159.81 ; 5.158,157.41 ccw(c5.158,159.81) 7.558,159.81 ; 5.158,162.21 cw(c5.158,159.81) 7.558,159.81 ; 5.158,162.21 cw(c5.158,159.81) 7.558,159.81 ; 207.418,5.174 ccw(c209.818,5.174) 209.818,2.774 ; 207.418,5.174 cw(c209.818,5.174) 209.818,7.574 ; 207.418,5.174 ccw(c209.818,5.174) 209.818,2.774 ; 207.418,5.174 cw(c209.818,5.174) 209.818,7.574 ; 207.418,159.81 ccw(c209.818,159.81) 209.818,157.41 ; 207.418,159.81 cw(c209.818,159.81) 209.818,162.21 ; 207.418,159.81 ccw(c209.818,159.81) 209.818,157.41 ; 207.418,159.81 cw(c209.818,159.81) 209.818,162.21 ; 209.818,2.774 ccw(c209.818,5.174) 212.218,5.174 ; 209.818,2.774 ccw(c209.818,5.174) 212.218,5.174 ; 209.818,7.574 cw(c209.818,5.174) 212.218,5.174 ; 209.818,7.574 cw(c209.818,5.174) 212.218,5.174 ; 209.818,157.41 ccw(c209.818,159.81) 212.218,159.81 ; 209.818,157.41 ccw(c209.818,159.81) 212.218,159.81 ; 209.818,162.21 cw(c209.818,159.81) 212.218,159.81 ; 209.818,162.21 cw(c209.818,159.81) 212.218,159.81 ; 213.468,0 ccw(c213.468,1.532) 215,1.532 ; 213.468,0 ccw(c213.468,1.532) 215,1.532 ; 213.468,0 ccw(c213.468,1.532) 215,1.532 ; 213.468,165 cw(c213.468,163.468) 215,163.468 ; 213.468,165 cw(c213.468,163.468) 215,163.468 ; 213.468,165 cw(c213.468,163.468) 215,163.468 ; 215,1.532 215,163.468 ; 215,1.532 215,163.468 ; 215,1.532 215,163.468
  text ".Layer_Name" at 14.656,-51.321 h1.52
M2 Board Dimensions:
  rectangle: 3.175,-39.675 12.7,-36.5
  rectangle: 0,-36.5 3.175,-33.325
  lines w0.178: 0,-36.5 25.4,-36.5 ; 3.175,-39.675 3.175,-33.325 ; 6.35,-39.675 6.35,-33.325 ; 12.7,-39.675 12.7,-33.325 ; 19.05,-39.675 19.05,-33.325 ; 0,-39.675 0,-33.325 25.4,-33.325 25.4,-39.675 0,-39.675
  text ".Layer_Name" at 14.656,-51.321 h1.52
M3 3D STEP Top:
  text ".Layer_Name" at 14.656,-51.321 h1.52
M4 3D STEP Bottom:
  text ".Layer_Name" at 14.656,-51.321 h1.52
M5 Assembly Top:
  lines w0.254: -7.417,-53.141 160.223,-53.141 ; -7.417,-47.976 160.274,-47.976 ; -7.417,-42.812 -7.417,-58.306 94.31,-58.306 160.274,-58.306 160.274,-42.812 -7.404,-42.812 -7.404,-58.306 32.614,-58.306 ; 55.194,-58.306 55.194,-42.812 ; 87.376,-47.976 87.376,-42.812 ; 108.712,-47.976 108.712,-42.812 ; 124.511,-58.471 124.511,-53.319
  text "COMPONENTS MARKED 'DNP' SHOULD NOT BE POPULATED." at 29.299,-37.605 h1.52
  text "ASSEMBLY VARIANT:" at 29.286,-40.538 h1.52
  text ".VariantName" at 55.601,-40.538 h1.52
  text "PCB VIEWED FROM TOP SIDE" at -5.804,-46.169 h1.52
  text "BOARD #:" at 57.099,-46.169 h1.52
  text ".PRJ_Number" at 70.955,-46.169 h1.52
  text "REV:" at 92.405,-46.169 h1.52
  text ".PCB_Rev" at 99.809,-46.169 h1.52
  text "SVN REV:" at 113.69,-46.169 h1.52
  text ".VersionControl_RevNumber" at 126.543,-46.169 h1.52
  text "TID #:" at 57.099,-51.333 h1.52
  text ".TID" at 70.955,-51.333 h1.52
  text "PLOT NAME =" at -5.804,-56.549 h1.52
  text ".plot_File_Name" at 14.656,-56.549 h1.52
  text "GENERATED    :" at 57.15,-56.549 h1.52
  text ".Print_Date" at 79.235,-56.549 h1.52
  text ".Print_Time" at 97.752,-56.549 h1.52
  text "TEXAS INSTRUMENTS" at 129.87,-56.549 h1.52
M6 Assembly Bottom:
  lines w0.254: -7.429,-47.989 160.261,-47.989 ; -7.379,-53.154 160.261,-53.154 ; 28.334,-58.483 28.334,-53.332 ; 44.133,-47.989 44.133,-42.824 ; 65.468,-47.989 65.468,-42.824 ; 97.65,-58.318 97.65,-42.824 ; 120.231,-58.318 160.249,-58.318 160.249,-42.824 -7.429,-42.824 -7.429,-58.318 58.534,-58.318 160.261,-58.318 160.261,-42.824
  text "COMPONENTS MARKED 'DNP' SHOULD NOT BE POPULATED." at 154.991,-37.592 h1.52
  text ".VariantName" at 128.473,-40.538 h1.52
  text "ASSEMBLY VARIANT:" at 154.864,-40.538 h1.52
  text ".VersionControl_RevNumber" at 26.302,-46.181 h1.52
  text "SVN REV:" at 39.154,-46.181 h1.52
  text ".PCB_Rev" at 53.035,-46.181 h1.52
  text "REV:" at 60.439,-46.181 h1.52
  text ".PRJ_Number" at 81.89,-46.181 h1.52
  text "BOARD #:" at 95.745,-46.181 h1.52
  text "PCB VIEWED FROM BOTTOM SIDE" at 158.648,-46.181 h1.52
  text ".TID" at 81.89,-51.346 h1.52
  text "TID #:" at 95.745,-51.346 h1.52
  text "TEXAS INSTRUMENTS" at 22.974,-56.562 h1.52
  text ".Print_Time" at 55.093,-56.562 h1.52
  text ".Print_Date" at 73.609,-56.562 h1.52
  text "GENERATED    :" at 95.694,-56.562 h1.52
  text ".plot_File_Name" at 138.189,-56.562 h1.52
  text "PLOT NAME =" at 158.648,-56.562 h1.52
M9 Title Sheet:
  drawing of 57 lines, arcs and shapes, not listed
  text "1" at 18.792,174.612 h1.78
  text "2" at 82.182,174.612 h1.78
  text "3" at 145.411,174.612 h1.78
  text "4" at 209.08,174.612 h1.78
  text "5" at 272.555,174.612 h1.78
  text "6" at 336.182,174.612 h1.78
  text "A" at -10.579,145.58 h1.78
  text "A" at 365.341,145.58 h1.78
  text "B" at -10.579,85.128 h1.78
  text "B" at 365.341,85.128 h1.78
  text "C" at -10.579,24.803 h1.78
  text "C" at 365.341,24.803 h1.78
  text "PROJECT TITLE:" at 288.125,-22.466 h1.14
  text ".PRJ_Title" at 289.395,-25.853 h1.78
  text "DESIGNED FOR:" at 288.125,-30.112 h1.14
  text ".PRJ_Customer" at 289.395,-33.668 h1.78
  text "D" at -10.579,-35.395 h1.78
  text "D" at 365.341,-35.395 h1.78
  text "FILE NAME:" at 288.125,-37.732 h1.14
  text ".PCB_File_Name_No_Path" at 289.395,-40.78 h1.78
  text "Texas Instruments (TI) and/or its licensors do not warrant the accuracy or completeness of this specification" at 161.9,-44.89 h1.14
  text "ENGINEER:" at 288.125,-45.098 h1.14
  text "LAYOUT BY:" at 326.352,-45.098 h1.14
  text "or any information contained therein. TI and/or its licensors do not warrant that this design will meet" at 160.757,-47.752 h1.14
  text ".PRJ_Engineer" at 289.395,-49.035 h1.78
  text ".PCB_Layout" at 327.635,-49.035 h1.78
  text "the specifications, will be suitable for your application or fit for any particular purpose, or will operate in" at 160.757,-50.614 h1.14
  text ".Layer_Name" at 14.656,-51.321 h1.52
  text "ALTIUM DESIGNER VERSION:" at 326.352,-52.972 h1.14
  text "an implementation. TI and/or its licensors do not warrant that the design is production worthy. You should" at 160.757,-53.475 h1.14
  text "completely validate and test your design implementation to confirm the system functionality for your application." at 161.9,-56.337 h1.14
  text ".print_Scale" at 289.395,-56.358 h1.78
  text ".Application_BuildNumber" at 327.635,-56.358 h1.78
  text "1" at 18.792,-61.608 h1.78
  text "2" at 82.182,-61.608 h1.78
  text "3" at 145.411,-61.608 h1.78
  text "4" at 209.08,-61.608 h1.78
  text "5" at 272.555,-61.608 h1.78
  text "6" at 336.182,-61.608 h1.78
M10 Fab Notes:
  drawing of 189 lines, arcs and shapes, not listed
  text "DESIGN INFORMATION" at 314.503,131.932 h1.52
  text "MIN. TRACK WIDTH:" at 298.131,128.576 h1.52
  text "8" at 325.976,128.576 h1.52
  text "MIL" at 329.907,128.576 h1.52
  text "MIN. CLEARANCE:" at 298.131,125.423 h1.52
  text "0.2" at 324.452,125.423 h1.52
  text "mm" at 329.907,125.423 h1.52
  text "MIN. VIA PAD SIZE:" at 298.131,122.27 h1.52
  text "24" at 325.214,122.27 h1.52
  text "MIL" at 329.907,122.27 h1.52
  text "0.05mm (2MIL)" at 315.784,118.971 h1.52
  text "MINIMUM ANNULAR RING" at 289.769,118.762 h1.52
  text "EXTERNAL" at 333.768,118.762 h1.52
  text "PER" at 294.849,115.965 h1.52
  text "IPC-D-275 CLASS 2 LEVEL C" at 300.437,115.965 h1.52
  text "MIL, HOLES" at 338.238,113.413 h1.52
  text "+/-" at 328.27,113.195 h1.52
  text "+/-" at 349.961,113.195 h1.52
  text "REGISTRATION TOLERANCES:" at 289.769,113.168 h1.52
  text "METAL" at 320.243,113.168 h1.52
  text "5" at 334.879,113.168 h1.52
  text "3" at 356.037,113.168 h1.52
  text "MIL" at 358.99,113.168 h1.52
  text "HOLE SIZE TOLERANCE (UNLESS OTHERWISE SPECIFIED):" at 289.769,110.67 h1.52
  text "+/-" at 349.961,110.597 h1.52
  text "3" at 356.037,110.571 h1.52
  text "MIL" at 358.99,110.57 h1.52
  text "MATERIAL:" at 287.87,107.074 h1.52
  text "FR-4 High Tg" at 312.926,103.81 h1.52
  text "X" at 309.257,103.607 h1.52
  text "FR-408" at 298.563,103.492 h1.52
  text "OTHER" at 336.358,103.492 h1.52
  text "62 MIL (1.6mm) +/-10%" at 306.694,99.859 h1.52
  text "X" at 303.643,99.797 h1.52
  text "THICKNESS:" at 289.769,99.65 h1.52
  text "OTHER" at 339.33,99.65 h1.52
  text "TOLERANCE:" at 289.769,96.137 h1.52
  text "X" at 311.314,96.137 h1.52
  text "ANSI IPC-6012 TYPE 3 CLASS 2" at 315.836,96.137 h1.52
  text "OTHER +/-" at 315.835,92.475 h1.52
  text "BOW & TWIST:" at 289.769,88.787 h1.52
  text "X" at 311.314,88.787 h1.52
  text "ANSI IPC-6012 TYPE 3 CLASS 2" at 315.836,88.787 h1.52
  text "OTHER +/-" at 315.835,85.061 h1.52
  text "DRILLING:" at 287.87,81.743 h1.52
  text "NC_DRILL FILES" at 332.599,79.071 h1.52
  text "REFERENCE:" at 289.769,78.971 h1.52
  text "X" at 306.463,78.969 h1.52
  text "AS SHOWN" at 310.984,78.971 h1.52
  text "X" at 329.348,78.971 h1.52
  text "OTHER" at 340.168,75.358 h1.52
  text "PTH COPPER THICKNESS:" at 289.761,75.268 h1.52
  text "X" at 318.697,75.268 h1.52
  text "20-30 um" at 321.948,75.268 h1.52
  text "BOARD FINISH:" at 287.87,71.519 h1.52
  text "SILKSCREEN:" at 291.812,68.722 h1.52
  text "X" at 316.14,68.722 h1.52
  text "TOP" at 319.112,68.722 h1.52
  text "X" at 329.094,68.722 h1.52
  text "BOTTOM" at 332.091,68.722 h1.52
  text "SILKSCREEN COLOR:" at 291.812,64.78 h1.52
  text "X" at 316.115,64.78 h1.52
  text "WHITE" at 319.112,64.78 h1.52
  text "OTHER" at 332.091,64.78 h1.52
  text "X" at 319.442,61.137 h1.52
  text "GREEN" at 322.439,61.137 h1.52
  text "OTHER" at 338.136,61.137 h1.52
  text "SOLDER RESIST COLOR:" at 291.812,60.962 h1.52
  text "X" at 319.442,57.219 h1.52
  text "MATTE" at 322.439,57.219 h1.52
  text "SEMI-GLOSS" at 338.125,57.203 h1.52
  text "IMMERSION GOLD (ENIG)" at 314.819,52.83 h1.52
  text "ENEPIG" at 348.793,52.647 h1.52
  text "SURFACE FINISH:" at 287.87,52.622 h1.52
  text "X" at 310.298,52.622 h1.52
  text "IMM. TIN/SILVER OR EQUIV" at 296.24,49.134 h1.52
  text "OTHER" at 332.599,49.034 h1.52
  text "ARRAY/PANEL:" at 287.87,45.087 h1.52
  text "CUT AND TRIM PER M1 BOARD OUTLINE" at 314.819,44.878 h1.52
  text "N.C. ROUTE" at 314.819,41.425 h1.52
  text "X" at 332.295,41.425 h1.52
  text "V. SCORE" at 336.816,41.425 h1.52
  text "CERTIFICATION:" at 287.87,38.145 h1.52
  text "MATERIALS AND WORKMANSHIP FOR ALL PCBS" at 306.285,38.145 h1.52
  text "TO MEET OR EXCEED THE REQUIREMENTS OF:" at 306.285,35.756 h1.52
  text "X" at 297.078,32.489 h1.52
  text "ANSI IPC-A-600F CLASS ->" at 300.329,32.489 h1.52
  text "X" at 342.188,32.489 h1.52
  text "2" at 344.982,32.489 h1.52
  text "1" at 336.981,32.451 h1.52
  text "3" at 353.973,32.451 h1.52
  text "X" at 317.702,28.737 h1.52
  text "RoHS" at 320.953,28.737 h1.52
  text "OTHER" at 337.321,28.737 h1.52
  text "PER ORDER" at 347.407,28.737 h1.52
  text "ALL BOARDS MUST MEET OR EXCEED UL94-V0 REQUIREMENTS." at 288.569,24.83 h1.52
  text "PCB MUST BEAR THE UL94V-0 UL REGISTERED MATERIAL ID NUMBER" at 288.569,21.882 h1.52
  text "ADDITIONAL REQUIREMENTS:" at 287.87,17.579 h1.52
  text "MICROSECTION:" at 289.769,14.858 h1.52
  text "YES" at 312.775,14.858 h1.52
  text "REQUIRED" at 334.657,11.192 h1.52
  text "BARE BOARD ELEC. TEST:" at 289.769,11.119 h1.52
  text "NONE" at 322.935,11.119 h1.52
  text "X" at 331.66,11.119 h1.52
  text "PER ORDER" at 349.693,11.119 h1.52
  text "XX MIL VIAS REQUIRE NON-CONDUCTIVE FILL AND PLANARIZE" at 294.04,5.914 h1.5
  text "XX MIL VIAS REQUIRE CONDUCTIVE FILL AND PLANARIZE" at 294.243,3.273 h1.52
  text "OUTER XX MIL TRACES REQUIRE 50 OHM SINGLE-ENDED IMPEDANCE" at 294.218,-0.877 h1.47
  text "LAYER 2 & 3 (INNER LAYERS) XX MIL WIDE, XX MIL SPACE / TRACES REQUIRE 100 OHM DIFFERENTIAL IMPEDANCE" at 294.015,-6.864 h1.52
  text ".Layer_Name" at 14.656,-51.321 h1.52
M11 Gerber Information:
  lines w0.254: -7.417,-53.141 160.223,-53.141 ; -7.417,-47.976 160.274,-47.976 ; -7.417,-42.812 -7.417,-58.306 94.31,-58.306 160.274,-58.306 160.274,-42.812 -7.404,-42.812 -7.404,-58.306 32.614,-58.306 ; 55.194,-58.306 55.194,-42.812 ; 87.376,-47.976 87.376,-42.812 ; 108.712,-47.976 108.712,-42.812 ; 124.511,-58.471 124.511,-53.319
  text "ALL ARTWORK VIEWED FROM TOP SIDE" at -5.804,-46.169 h1.52
  text "BOARD #:" at 57.099,-46.169 h1.52
  text ".PRJ_Number" at 70.955,-46.169 h1.52
  text "REV:" at 92.405,-46.169 h1.52
  text ".PCB_Rev" at 99.809,-46.169 h1.52
  text "SVN REV:" at 113.69,-46.169 h1.52
  text ".VersionControl_RevNumber" at 126.543,-46.169 h1.52
  text "LAYER NAME =" at -5.804,-51.321 h1.52
  text "TID #:" at 57.099,-51.333 h1.52
  text ".TID" at 70.955,-51.333 h1.52
  text "PLOT NAME =" at -5.804,-56.549 h1.52
  text ".plot_File_Name" at 14.656,-56.549 h1.52
  text "GENERATED    :" at 57.15,-56.549 h1.52
  text ".Print_Date" at 79.235,-56.549 h1.52
  text ".Print_Time" at 97.752,-56.549 h1.52
  text "TEXAS INSTRUMENTS" at 129.87,-56.549 h1.52
M12 Stackup:
  drawing of 382 lines, arcs and shapes, not listed
  text "Layer" at 248.668,168.084 h1.52
  text "Layer" at 248.668,168.084 h1.52
  text "Name" at 259.08,168.084 h1.52
  text "Name" at 259.08,168.084 h1.52
  text "Material" at 282.696,168.084 h1.52
  text "Material" at 282.696,168.084 h1.52
  text "Thickness" at 304.534,168.084 h1.52
  text "Thickness" at 304.534,168.084 h1.52
  text "Constant" at 321.039,168.084 h1.52
  text "Constant" at 321.039,168.084 h1.52
  text "Board Layer Stack" at 335.514,168.084 h1.52
  text "Board Layer Stack" at 335.514,168.084 h1.52
  text "1" at 248.668,165.036 h1.52
  text "1" at 248.668,165.036 h1.52
  text "Top Overlay" at 259.08,165.036 h1.52
  text "Top Overlay" at 259.08,165.036 h1.52
  text "2" at 248.668,161.988 h1.52
  text "2" at 248.668,161.988 h1.52
  text "Top Solder" at 259.08,161.988 h1.52
  text "Top Solder" at 259.08,161.988 h1.52
  text "Solder Resist" at 282.696,161.988 h1.52
  text "Solder Resist" at 282.696,161.988 h1.52
  text "0.40mil" at 304.534,161.988 h1.52
  text "0.40mil" at 304.534,161.988 h1.52
  text "3.5" at 321.039,161.988 h1.52
  text "3.5" at 321.039,161.988 h1.52
  text "3" at 248.668,158.94 h1.52
  text "3" at 248.668,158.94 h1.52
  text "Top Layer" at 259.08,158.94 h1.52
  text "Top Layer" at 259.08,158.94 h1.52
  text "Copper" at 282.696,158.94 h1.52
  text "Copper" at 282.696,158.94 h1.52
  text "1.40mil" at 304.534,158.94 h1.52
  text "1.40mil" at 304.534,158.94 h1.52
  text "4" at 248.668,155.892 h1.52
  text "4" at 248.668,155.892 h1.52
  text "Dielectric1" at 259.08,155.892 h1.52
  text "Dielectric1" at 259.08,155.892 h1.52
  text "FR-4" at 282.696,155.892 h1.52
  text "FR-4" at 282.696,155.892 h1.52
  text "59.20mil" at 304.534,155.892 h1.52
  text "59.20mil" at 304.534,155.892 h1.52
  text "4.8" at 321.039,155.892 h1.52
  text "4.8" at 321.039,155.892 h1.52
  text "5" at 248.668,152.844 h1.52
  text "5" at 248.668,152.844 h1.52
  text "Bottom Layer" at 259.08,152.844 h1.52
  text "Bottom Layer" at 259.08,152.844 h1.52
  text "Copper" at 282.696,152.844 h1.52
  text "Copper" at 282.696,152.844 h1.52
  text "1.40mil" at 304.534,152.844 h1.52
  text "1.40mil" at 304.534,152.844 h1.52
  text "6" at 248.668,149.796 h1.52
  text "6" at 248.668,149.796 h1.52
  text "Bottom Solder" at 259.08,149.796 h1.52
  text "Bottom Solder" at 259.08,149.796 h1.52
  text "Solder Resist" at 282.696,149.796 h1.52
  text "Solder Resist" at 282.696,149.796 h1.52
  text "0.40mil" at 304.534,149.796 h1.52
  text "0.40mil" at 304.534,149.796 h1.52
  text "3.5" at 321.039,149.796 h1.52
  text "3.5" at 321.039,149.796 h1.52
  text "7" at 248.668,146.749 h1.52
  text "7" at 248.668,146.749 h1.52
  text "Bottom Overlay" at 259.08,146.749 h1.52
  text "Bottom Overlay" at 259.08,146.749 h1.52
  text ".Layer_Name" at 14.656,-51.321 h1.52
M13 Component Bodies Top:
  text ".Layer_Name" at 14.656,-51.321 h1.52
M14 Component Bodies Bottom:
  text ".Layer_Name" at 14.656,-51.321 h1.52
M15 Courtyards Top:
  text ".Layer_Name" at 14.656,-51.321 h1.52
M16 Courtyards Bottom:
  text ".Layer_Name" at 14.656,-51.321 h1.52
Drill Drawing:
  drawing of 183 lines, arcs and shapes, not listed
  text "Symbol" at 217.989,132.443 h1.83
  text "Quantity" at 225.623,132.443 h1.83
  text "Finished Hole Size" at 234.056,132.443 h1.83
  text "Plated" at 250.225,132.443 h1.83
  text "Hole Type" at 256.807,132.443 h1.83
  text "Drill Layer Pair" at 266.336,132.443 h1.83
  text "4" at 225.623,129.285 h1.52
  text "141.73mil (3.600mm)" at 234.056,129.285 h1.52
  text "NPTH" at 250.225,129.285 h1.52
  text "Round" at 256.807,129.285 h1.52
  text "Top Layer - Bottom Layer" at 266.336,129.285 h1.52
  text "L" at 217.347,129.032 h1.4
  text "2" at 225.623,126.128 h1.52
  text "29.53mil (0.750mm)" at 234.056,126.128 h1.52
  text "PTH" at 250.225,126.128 h1.52
  text "Round" at 256.807,126.128 h1.52
  text "Top Layer - Bottom Layer" at 266.336,126.128 h1.52
  text "F" at 217.347,125.874 h1.4
  text "6" at 225.623,122.97 h1.52
  text "30.00mil (0.762mm)" at 234.056,122.97 h1.52
  text "PTH" at 250.225,122.97 h1.52
  text "Round" at 256.807,122.97 h1.52
  text "Top Layer - Bottom Layer" at 266.336,122.97 h1.52
  text "G" at 217.347,122.716 h1.4
  text "22" at 225.623,119.812 h1.52
  text "31.50mil (0.800mm)" at 234.056,119.812 h1.52
  text "PTH" at 250.225,119.812 h1.52
  text "Round" at 256.807,119.812 h1.52
  text "Top Layer - Bottom Layer" at 266.336,119.812 h1.52
  text "24" at 225.623,116.655 h1.52
  text "33.47mil (0.850mm)" at 234.056,116.655 h1.52
  text "PTH" at 250.225,116.655 h1.52
  text "Round" at 256.807,116.655 h1.52
  text "Top Layer - Bottom Layer" at 266.336,116.655 h1.52
  text "18" at 225.623,113.497 h1.52
  text "35.43mil (0.900mm)" at 234.056,113.497 h1.52
  text "PTH" at 250.225,113.497 h1.52
  text "Round" at 256.807,113.497 h1.52
  text "Top Layer - Bottom Layer" at 266.336,113.497 h1.52
  text "14" at 225.623,110.339 h1.52
  text "37.00mil (0.940mm)" at 234.056,110.339 h1.52
  text "PTH" at 250.225,110.339 h1.52
  text "Round" at 256.807,110.339 h1.52
  text "Top Layer - Bottom Layer" at 266.336,110.339 h1.52
  text "2" at 225.623,107.181 h1.52
  text "37.40mil (0.950mm)" at 234.056,107.181 h1.52
  text "PTH" at 250.225,107.181 h1.52
  text "Round" at 256.807,107.181 h1.52
  text "Top Layer - Bottom Layer" at 266.336,107.181 h1.52
  text "10" at 225.623,104.024 h1.52
  text "38.00mil (0.965mm)" at 234.056,104.024 h1.52
  text "PTH" at 250.225,104.024 h1.52
  text "Round" at 256.807,104.024 h1.52
  text "Top Layer - Bottom Layer" at 266.336,104.024 h1.52
  text "I" at 217.58,103.77 h1.4
  text "2" at 225.623,100.866 h1.52
  text "40.00mil (1.016mm)" at 234.056,100.866 h1.52
  text "PTH" at 250.225,100.866 h1.52
  text "Round" at 256.807,100.866 h1.52
  text "Top Layer - Bottom Layer" at 266.336,100.866 h1.52
  text "4" at 225.623,97.708 h1.52
  text "41.34mil (1.050mm)" at 234.056,97.708 h1.52
  text "PTH" at 250.225,97.708 h1.52
  text "Round" at 256.807,97.708 h1.52
  text "Top Layer - Bottom Layer" at 266.336,97.708 h1.52
  text "6" at 225.623,94.55 h1.52
  text "43.31mil (1.100mm)" at 234.056,94.55 h1.52
  text "PTH" at 250.225,94.55 h1.52
  text "Round" at 256.807,94.55 h1.52
  text "Top Layer - Bottom Layer" at 266.336,94.55 h1.52
  text "8" at 225.623,91.393 h1.52
  text "45.28mil (1.150mm)" at 234.056,91.393 h1.52
  text "PTH" at 250.225,91.393 h1.52
  text "Round" at 256.807,91.393 h1.52
  text "Top Layer - Bottom Layer" at 266.336,91.393 h1.52
  text "H" at 217.347,91.139 h1.4
  text "23" at 225.623,88.235 h1.52
  text "47.24mil (1.200mm)" at 234.056,88.235 h1.52
  text "PTH" at 250.225,88.235 h1.52
  text "Round" at 256.807,88.235 h1.52
  text "Top Layer - Bottom Layer" at 266.336,88.235 h1.52
  text "K" at 217.347,87.981 h1.4
  text "26" at 225.623,85.077 h1.52
  text "51.18mil (1.300mm)" at 234.056,85.077 h1.52
  text "PTH" at 250.225,85.077 h1.52
  text "Round" at 256.807,85.077 h1.52
  text "Top Layer - Bottom Layer" at 266.336,85.077 h1.52
  text "5" at 225.623,81.92 h1.52
  text "59.06mil (1.500mm)" at 234.056,81.92 h1.52
  text "PTH" at 250.225,81.92 h1.52
  text "Round" at 256.807,81.92 h1.52
  text "Top Layer - Bottom Layer" at 266.336,81.92 h1.52
  text "E" at 217.347,81.666 h1.4
  text "4" at 225.623,78.762 h1.52
  text "61.02mil (1.550mm)" at 234.056,78.762 h1.52
  text "PTH" at 250.225,78.762 h1.52
  text "Round" at 256.807,78.762 h1.52
  text "Top Layer - Bottom Layer" at 266.336,78.762 h1.52
  text "7" at 225.623,75.604 h1.52
  text "63.00mil (1.600mm)" at 234.056,75.604 h1.52
  text "PTH" at 250.225,75.604 h1.52
  text "Round" at 256.807,75.604 h1.52
  text "Top Layer - Bottom Layer" at 266.336,75.604 h1.52
  text "D" at 217.347,75.35 h1.4
  text "13" at 225.623,72.446 h1.52
  text "70.87mil (1.800mm)" at 234.056,72.446 h1.52
  text "PTH" at 250.225,72.446 h1.52
  text "Round" at 256.807,72.446 h1.52
  text "Top Layer - Bottom Layer" at 266.336,72.446 h1.52
  text "J" at 217.347,72.193 h1.4
  text "14" at 225.623,69.289 h1.52
  text "78.74mil (2.000mm)" at 234.056,69.289 h1.52
  text "PTH" at 250.225,69.289 h1.52
  text "Round" at 256.807,69.289 h1.52
  text "Top Layer - Bottom Layer" at 266.336,69.289 h1.52
  text "2" at 225.623,66.131 h1.52
  text "122.05mil (3.100mm)" at 234.056,66.131 h1.52
  text "PTH" at 250.225,66.131 h1.52
  text "Round" at 256.807,66.131 h1.52
  text "Top Layer - Bottom Layer" at 266.336,66.131 h1.52
  text "3" at 225.623,62.973 h1.52
  text "129.92mil (3.300mm)" at 234.056,62.973 h1.52
  text "PTH" at 250.225,62.973 h1.52
  text "Round" at 256.807,62.973 h1.52
  text "Top Layer - Bottom Layer" at 266.336,62.973 h1.52
  text "2" at 225.623,59.815 h1.52
  text "39.37mil (1.000mm)" at 234.056,59.815 h1.52
  text "NPTH" at 250.225,59.815 h1.52
  text "Slot" at 256.807,59.815 h1.52
  text "Top Layer - Bottom Layer" at 266.336,59.815 h1.52
  text "2" at 225.623,56.658 h1.52
  text "39.37mil (1.000mm)" at 234.056,56.658 h1.52
  text "NPTH" at 250.225,56.658 h1.52
  text "Slot" at 256.807,56.658 h1.52
  text "Top Layer - Bottom Layer" at 266.336,56.658 h1.52
  text "4" at 225.623,53.5 h1.52
  text "39.37mil (1.000mm)" at 234.056,53.5 h1.52
  text "PTH" at 250.225,53.5 h1.52
  text "Slot" at 256.807,53.5 h1.52
  text "Top Layer - Bottom Layer" at 266.336,53.5 h1.52
  text "A" at 217.347,53.246 h1.4
  text "4" at 225.623,50.342 h1.52
  text "43.31mil (1.100mm)" at 234.056,50.342 h1.52
  text "PTH" at 250.225,50.342 h1.52
  text "Slot" at 256.807,50.342 h1.52
  text "Top Layer - Bottom Layer" at 266.336,50.342 h1.52
  text "B" at 217.347,50.088 h1.4
  text "4" at 225.623,47.185 h1.52
  text "43.31mil (1.100mm)" at 234.056,47.185 h1.52
  text "PTH" at 250.225,47.185 h1.52
  text "Slot" at 256.807,47.185 h1.52
  text "Top Layer - Bottom Layer" at 266.336,47.185 h1.52
  text "C" at 217.347,46.931 h1.4
  text "235 Total" at 225.623,44.027 h1.52
  text "Slot definitions :" at 217.989,41.816 h1.52
  text "Routed Path Length" at 229.437,41.816 h1.52
  text "= Calculated from tool start centre position to tool end centre position." at 243.146,41.816 h1.52
  text "Hole Length" at 229.437,40.553 h1.52
  text "= Routed Path Length + Tool Size = Slot length as defined in the PCB layout" at 238.072,40.553 h1.52
  text ".Layer_Name" at 14.656,-51.321 h1.52
M17 Embedded Cavity:
  text ".Layer_Name" at 14.656,-51.321 h1.52
M18 Embedded Assembly:
  text ".Layer_Name" at 14.656,-51.321 h1.52
M19 Embedded Keepout:
  text ".Layer_Name" at 14.656,-51.321 h1.52

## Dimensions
0,1.532 to 215,1.532 on M2 Board Dimensions
1.532,0 to 1.532,165 on M2 Board Dimensions
0,-39.675 to 25.4,-39.675 on M2 Board Dimensions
